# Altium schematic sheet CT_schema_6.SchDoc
size 242 x 245 mm
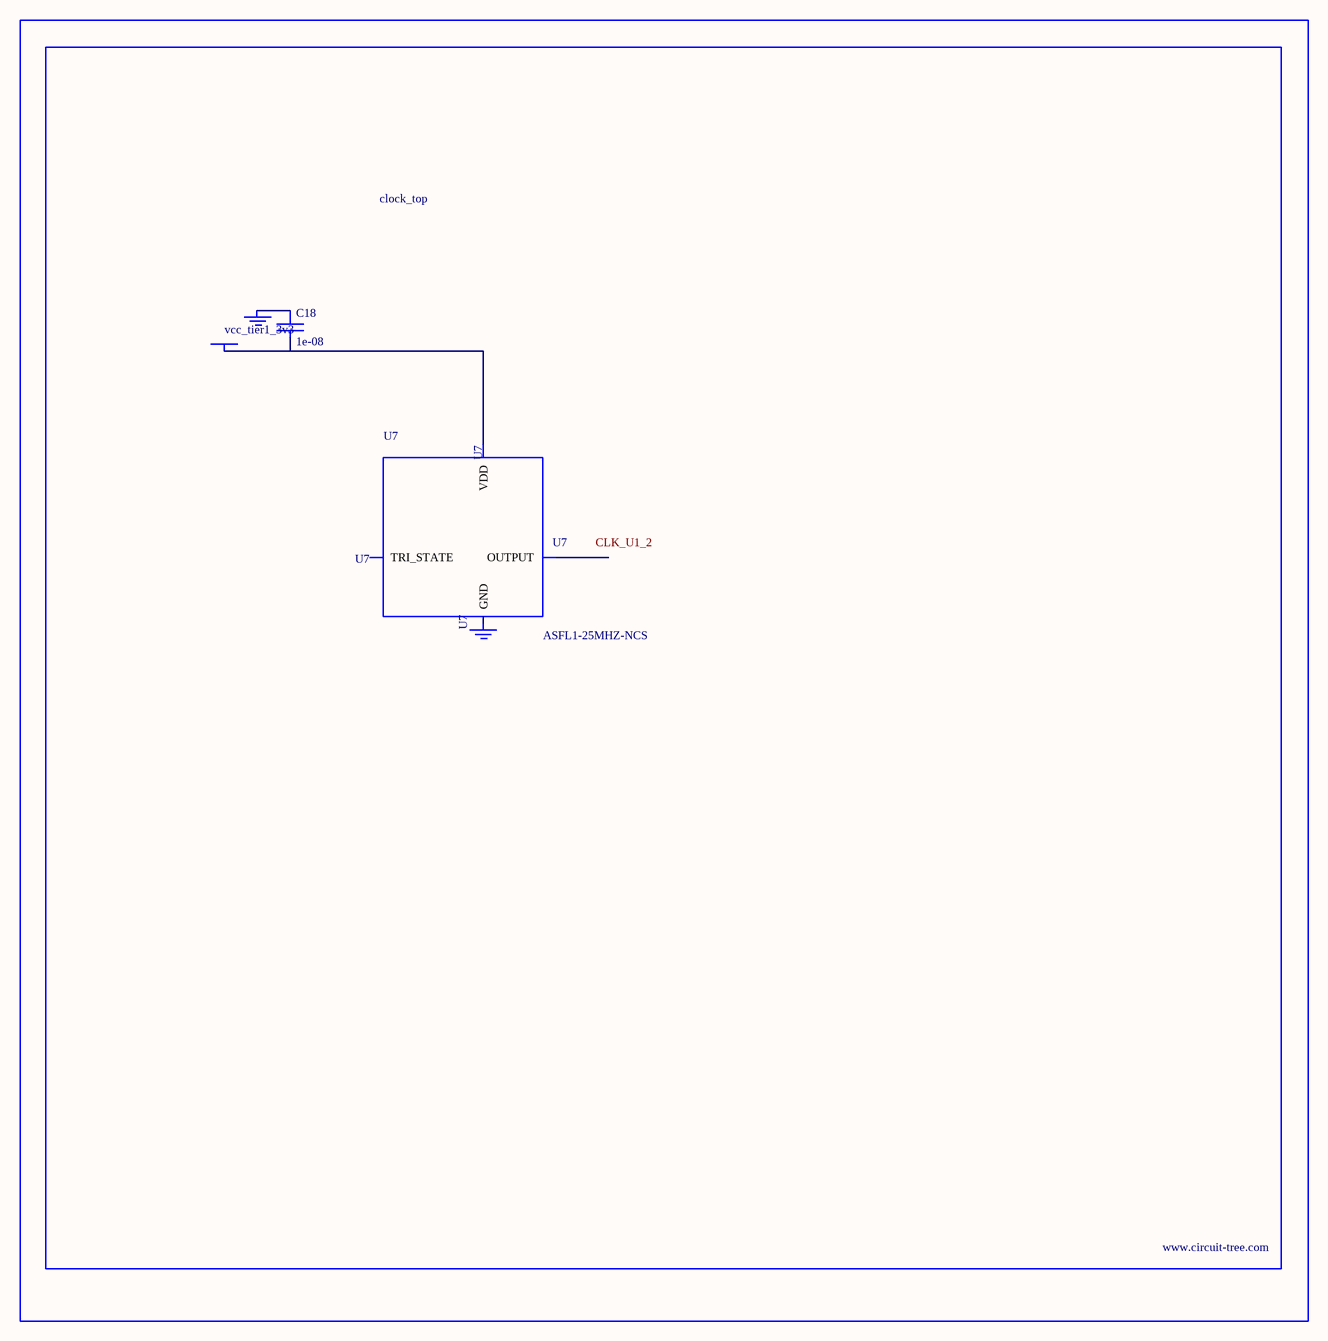
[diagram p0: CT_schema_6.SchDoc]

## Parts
BORDER5  (no value)
C18  1e-08  [C0402]
GND_INSTANCE_5_0  (no value)
GND_INSTANCE_5_1  (no value)
POWER_INSTANCE_5_0  vcc_tier1_3v3
U7  ASFL1-25MHZ-NCS  [ASFL1]

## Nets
NetC18_1: C18.1 GND_INSTANCE_5_0.0(GND)
NetC18_2: C18.2 POWER_INSTANCE_5_0.0(PWR) U7.4(VDD)

Not connected (* = marked no-connect by the designer): GND_INSTANCE_5_1 0(GND); U7 1(TRI_STATE) 2(GND) 3(OUTPUT)

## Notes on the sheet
- Labels drawn without touching a wire or pin: CLK_U1_2

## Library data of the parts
BORDER5 = BORDER_PAGE5
C18 = C0402C103K3RAC
GND_INSTANCE_5_0 GND_INSTANCE_5_1 = GND
POWER_INSTANCE_5_0 = PWR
